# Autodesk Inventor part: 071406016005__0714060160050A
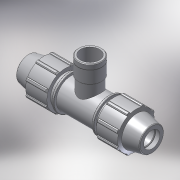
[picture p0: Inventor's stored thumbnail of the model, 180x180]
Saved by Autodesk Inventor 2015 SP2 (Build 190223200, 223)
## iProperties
Created: 2017-02
Part Number: 071406016005__0714060160050A
Material: PVC-Piping
Description: PLASSON TEE WITH THREADED FEMALE OFFTAKE 16-1/2"-16
Document SubType Name: Modeling
Designer: KIM
Mass: 92.6774 g
Surface Area: 199.44 cm^2
Volume: 66.1981 cm^3
Density: 1.4 g/cm^3
Appearance: Smooth - White
Author: KIM
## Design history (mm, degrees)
derived "07140.ipt"
feature "Solid1::07140.ipt"
feature "Solid2::07140.ipt"
tag "TaggingFeature1"
body "Solid1"
other parameters: "d2" = 16, "d4" = 5.08333, "d5" = 14.64, "d7" = 39, "d11" = 2.03333, "d13" = 120 deg, "d14" = 24, "d15" = 12 deg, "d16" = 33.93, "d18" = 0.8, "d19" = 35 deg, "d20" = 17.5 deg, "d21" = 36.27, "d23" = 0, "d25" = 360 deg, "d27" = 0.78, "d33" = 0.32, "d42" = 21.96, "d43" = 1.17, "d46" = 0.48, "d68" = 3.66, "d72" = 42, "d76" = 18.631, "d80" = 0.55893, "d91" = 29.25, "d95" = 14.4, "d112" = 17, "d115" = 23.28875, "d116" = 135 deg, "d117" = 21.42565, "d118" = 122, "d119" = 14.4, "d121" = 0, "d122" = 14.4, "d124" = 0, "d128" = 0, "d129" = 1.6, "d130" = 5.1, "d131" = 0.3, "d132" = 0.3, "d133" = 23.28875, "d_" = 16, "E_" = 39, "A_" = 42, "l_2" = 17, "Rp_" = 18.631, "H_" = 122
